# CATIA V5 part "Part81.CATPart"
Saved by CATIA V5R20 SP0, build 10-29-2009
Part number: FA 053000-2
Revision: ANY
Definition: UNKNOWN
Nomenclature: FA 053000-2
Source: Unknown
Bounding box of the stored display mesh (mm): x -1.5 to 1.5, y 0 to 3.7, z -1.5 to 1.5
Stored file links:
  C:\Users\Utente\Desktop\IO LAVORO\3D X SITO CF\CUMSA\3D files FA\FA 053012-20\Part81.CATPart

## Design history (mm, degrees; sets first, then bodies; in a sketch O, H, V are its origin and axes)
Body1 "Cortar-Extruir1" (main body)
  Solid1: solid without history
